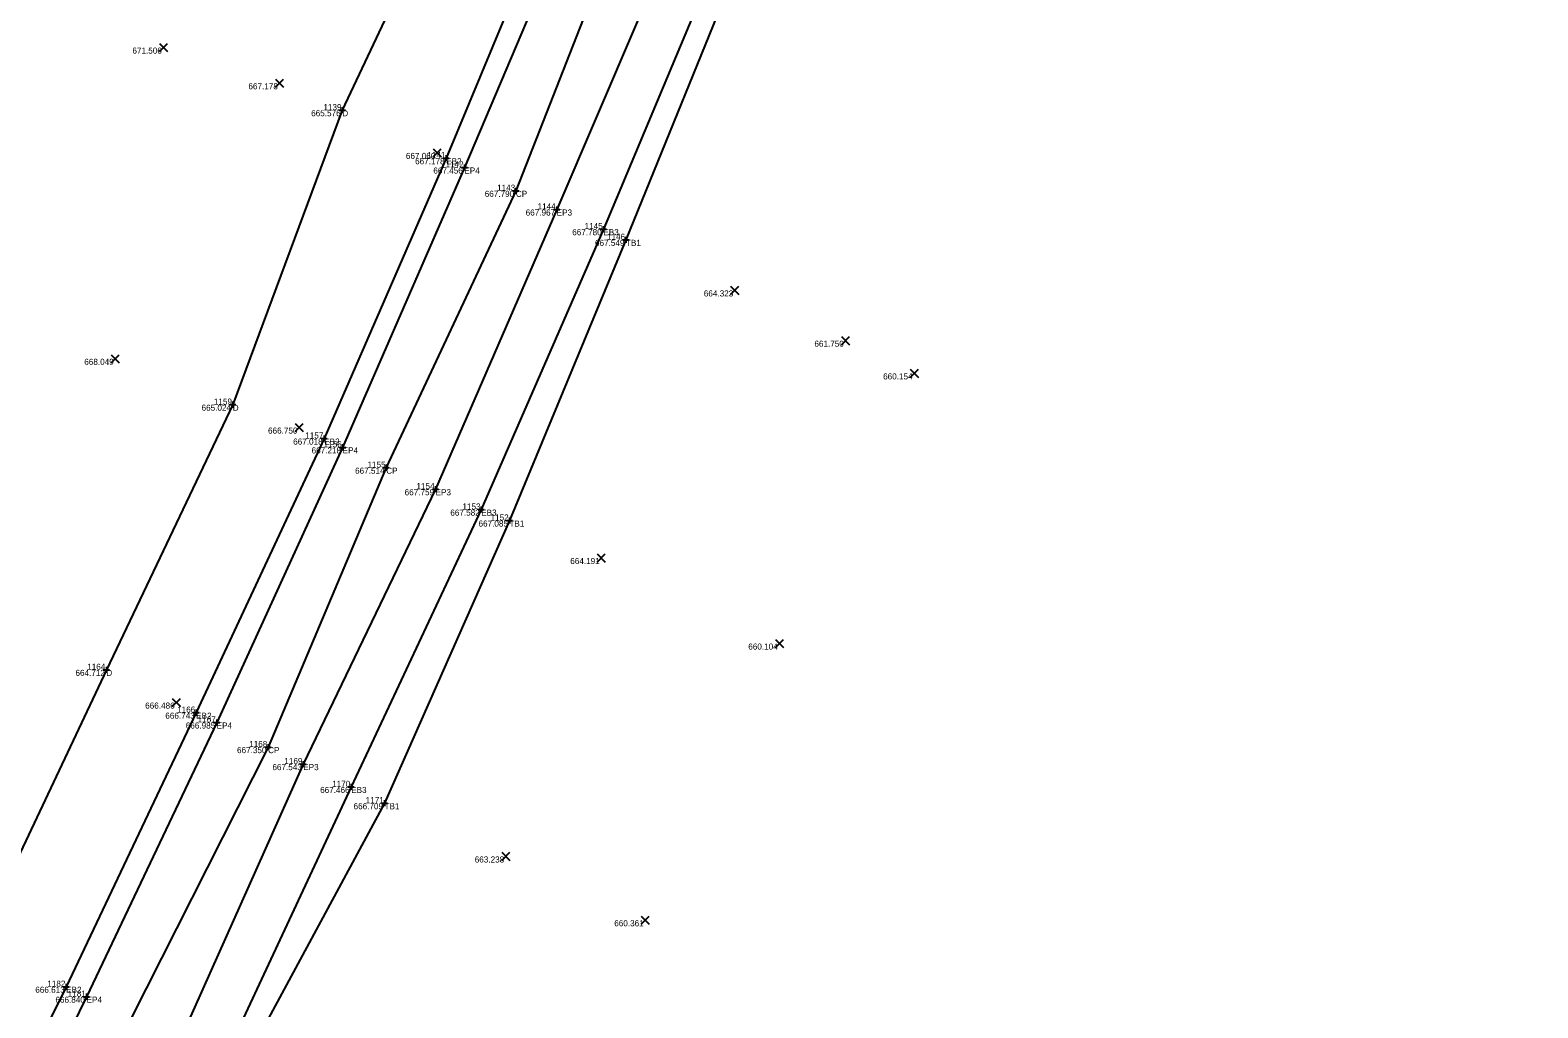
# Model space of a CAD drawing. Extents: x 2197382 to 2204062, y 634117 to 636522.
# Drawn here: x 2203093 to 2203340.5, y 635874.6 to 636035.1 of the extents above; entities that cross this region are included whole.
import ezdxf

# ---------------------------------------------------------------- set-up
doc = ezdxf.new("R2010")
doc.units = 0
for name, color, linetype in [('_CIVIL_CONSTRUCTION', 7, 'Continuous'), ('DR_X_Ditch', 7, 'Continuous'), ('GE_P_Alignment_100_Distances', 7, 'Continuous'), ('GE_X_Alignment', 7, 'Continuous'), ('PF_P_Grade_Line', 7, 'Continuous'), ('PV_X_COP', 7, 'Continuous'), ('RW_X_CL_100_Curve_Data', 7, 'Continuous'), ('SH_Border', 7, 'Continuous'), ('SH_Cut_Line', 7, 'Continuous'), ('SH_Data', 7, 'Continuous')]:
    doc.layers.add(name, color=color, linetype=linetype)

msp = doc.modelspace()

# ---------------------------------------------------------------- linework, layer by layer
at = {"layer": '_CIVIL_CONSTRUCTION'}
for p, q in [((2203143.75, 636021.99), (2203144.75, 636021.99)), ((2203144.25, 636022.49), (2203144.25, 636021.49)), ((2203144.25, 636021.99), (2203144.25, 636021.99)), ((2203160.8, 636014.11), (2203161.8, 636014.11)), ((2203161.3, 636014.61), (2203161.3, 636013.61)), ((2203161.3, 636014.11), (2203161.3, 636014.11)), ((2203163.79, 636012.58), (2203164.79, 636012.58)), ((2203164.29, 636013.08), (2203164.29, 636012.08)), ((2203164.29, 636012.58), (2203164.29, 636012.58)), ((2203172.24, 636008.76), (2203173.24, 636008.76)), ((2203172.74, 636009.26), (2203172.74, 636008.26)), ((2203172.74, 636008.76), (2203172.74, 636008.76)), ((2203178.94, 636005.69), (2203179.94, 636005.69)), ((2203179.44, 636006.19), (2203179.44, 636005.19)), ((2203179.44, 636005.69), (2203179.44, 636005.69)), ((2203186.6, 636002.46), (2203187.6, 636002.46)), ((2203187.1, 636002.96), (2203187.1, 636001.96)), ((2203187.1, 636002.46), (2203187.1, 636002.46)), ((2203190.81, 636001.21), (2203190.81, 636000.21)), ((2203190.31, 636000.71), (2203191.31, 636000.71)), ((2203190.81, 636000.71), (2203190.81, 636000.71)), ((2203125.77, 635973.65), (2203126.77, 635973.65)), ((2203126.27, 635974.15), (2203126.27, 635973.15)), ((2203126.27, 635973.65), (2203126.27, 635973.65)), ((2203141.29, 635968.59), (2203141.29, 635967.59)), ((2203140.79, 635968.09), (2203141.79, 635968.09)), ((2203141.29, 635968.09), (2203141.29, 635968.09)), ((2203143.81, 635966.64), (2203144.81, 635966.64)), ((2203144.31, 635967.14), (2203144.31, 635966.14)), ((2203144.31, 635966.64), (2203144.31, 635966.64)), ((2203151.47, 635963.81), (2203151.47, 635962.81)), ((2203150.97, 635963.31), (2203151.97, 635963.31)), ((2203151.47, 635963.31), (2203151.47, 635963.31)), ((2203159.06, 635959.77), (2203160.06, 635959.77)), ((2203159.56, 635960.27), (2203159.56, 635959.27)), ((2203159.56, 635959.77), (2203159.56, 635959.77)), ((2203166.55, 635956.43), (2203167.55, 635956.43)), ((2203167.05, 635956.93), (2203167.05, 635955.93)), ((2203167.05, 635956.43), (2203167.05, 635956.43)), ((2203171.18, 635954.63), (2203172.18, 635954.63)), ((2203171.68, 635955.13), (2203171.68, 635954.13)), ((2203171.68, 635954.63), (2203171.68, 635954.63)), ((2203105.02, 635930.12), (2203106.02, 635930.12)), ((2203105.52, 635930.62), (2203105.52, 635929.62)), ((2203105.52, 635930.12), (2203105.52, 635930.12)), ((2203119.76, 635923.09), (2203120.76, 635923.09)), ((2203120.26, 635923.59), (2203120.26, 635922.59)), ((2203120.26, 635923.09), (2203120.26, 635923.09)), ((2203123.63, 635921.98), (2203123.63, 635920.98)), ((2203123.13, 635921.48), (2203124.13, 635921.48)), ((2203123.63, 635921.48), (2203123.63, 635921.48)), ((2203131.58, 635917.44), (2203132.58, 635917.44)), ((2203132.08, 635917.94), (2203132.08, 635916.94)), ((2203132.08, 635917.44), (2203132.08, 635917.44)), ((2203137.34, 635914.65), (2203138.34, 635914.65)), ((2203137.84, 635915.15), (2203137.84, 635914.15)), ((2203137.84, 635914.65), (2203137.84, 635914.65)), ((2203145.21, 635910.9), (2203146.21, 635910.9)), ((2203145.71, 635911.4), (2203145.71, 635910.4)), ((2203145.71, 635910.9), (2203145.71, 635910.9)), ((2203150.69, 635908.23), (2203151.69, 635908.23)), ((2203151.19, 635908.73), (2203151.19, 635907.73)), ((2203151.19, 635908.23), (2203151.19, 635908.23)), ((2203098.42, 635878.1), (2203099.42, 635878.1)), ((2203098.92, 635878.6), (2203098.92, 635877.6)), ((2203098.92, 635878.1), (2203098.92, 635878.1)), ((2203101.78, 635876.46), (2203102.78, 635876.46)), ((2203102.28, 635876.96), (2203102.28, 635875.96)), ((2203102.28, 635876.46), (2203102.28, 635876.46))]:
    msp.add_line(p, q, dxfattribs=at)
at = {"layer": 'DR_X_Ditch'}
msp.add_lwpolyline([(2203184.1, 636112.24), (2203164.63, 636065.3), (2203144.25, 636021.99), (2203126.27, 635973.65), (2203105.52, 635930.12), (2203083.98, 635884.54), (2203067.89, 635850.01), (2203034.81, 635789.04), (2203015.61, 635755.76), (2202991.81, 635713.71), (2202963.02, 635673.98)], dxfattribs=at)
at = {"layer": 'GE_P_Alignment_100_Distances'}
for points in [[(2203324.48, 636507.85), (2203318.62, 636484.14), (2203306.91, 636435.63), (2203294.22, 636387.53), (2203281.02, 636340.01), (2203266.86, 636291.74), (2203251.88, 636244.73), (2203235.99, 636197.91), (2203219.31, 636150.6), (2203201.96, 636104.73), (2203183.73, 636058.36), (2203164.29, 636012.58), (2203144.31, 635966.64), (2203123.63, 635921.48), (2203102.28, 635876.46), (2203085.37, 635841.98), (2203051.94, 635779.64), (2203032.08, 635745.73), (2203005.62, 635703.58), (2202977.57, 635663.01), (2202948.44, 635623.54), (2202917.31, 635585.47), (2202885.13, 635547.53), (2202851.31, 635511.58)], [(2203340.49, 636502.89), (2203334.83, 636480.1), (2203323.13, 636431.59), (2203310.29, 636383.13), (2203297.23, 636335.04), (2203282.66, 636287.13), (2203267.38, 636239.56), (2203251.38, 636192.17), (2203234.81, 636145.08), (2203217.29, 636098.29), (2203199.14, 636051.74), (2203179.44, 636005.69), (2203159.56, 635959.77), (2203137.84, 635914.65), (2203117.45, 635869.06), (2203100.66, 635835.13), (2203066.13, 635771.41), (2203046.09, 635737.06), (2203019.37, 635694.82), (2202991.01, 635653.88), (2202961.19, 635613.48), (2202929.73, 635574.61), (2202897.41, 635536.46), (2202863.17, 635499.96)]]:
    msp.add_lwpolyline(points, dxfattribs=at)
at = {"layer": 'GE_X_Alignment'}
for points in [[(2203321.2, 636508.87), (2203315.42, 636484.99), (2203303.56, 636436.4), (2203290.91, 636388.48), (2203277.67, 636341.19), (2203263.29, 636292.83), (2203248.5, 636245.95), (2203232.65, 636199.01), (2203215.82, 636151.66), (2203198.58, 636105.93), (2203180.2, 636059.59), (2203161.3, 636014.11), (2203141.29, 635968.09), (2203120.26, 635923.09), (2203098.92, 635878.1), (2203081.73, 635843.65), (2203048.56, 635781.48), (2203029.15, 635747.49), (2203002.61, 635705.63), (2202974.64, 635665.31), (2202945.56, 635625.56), (2202914.38, 635588.2), (2202882.41, 635550.01), (2202847.99, 635514.11)], [(2203331.27, 636429.38), (2203318.29, 636380.99), (2203304.79, 636332.88), (2203290.18, 636284.77), (2203275.23, 636236.57), (2203259.29, 636189.41), (2203242.5, 636142.16), (2203224.73, 636095.35), (2203206.44, 636048.57), (2203187.1, 636002.46), (2203167.05, 635956.43), (2203145.71, 635910.9), (2203124.58, 635865.62), (2203107.54, 635831.47), (2203073.07, 635766.88), (2203053.33, 635732.69), (2203026.37, 635690.11), (2202997.51, 635648.24), (2202967.93, 635608.32), (2202935.99, 635569.18), (2202902.86, 635531.15), (2202868.61, 635494.33)]]:
    msp.add_lwpolyline(points, dxfattribs=at)
at = {"layer": 'PF_P_Grade_Line'}
msp.add_lwpolyline([(2203263.6, 636187.64), (2203248.97, 636139.91), (2203228.73, 636093.53), (2203209.69, 636047.17), (2203190.81, 636000.71), (2203171.68, 635954.63), (2203151.19, 635908.23), (2203127.58, 635864.5), (2203111.43, 635829.11), (2203075.98, 635764.92), (2203057.74, 635729.87), (2203030.91, 635688.09), (2203003.19, 635643.55), (2202971.04, 635606.63), (2202940.16, 635565.41)], dxfattribs=at)
at = {"layer": 'PV_X_COP'}
msp.add_lwpolyline([(2203333.12, 636504.55), (2203327.23, 636481.85), (2203314.64, 636433.62), (2203302.94, 636385.15), (2203289.25, 636336.51), (2203274.73, 636289.23), (2203259.31, 636242.63), (2203243.41, 636195.32), (2203226.43, 636148.15), (2203210.06, 636101.18), (2203190.93, 636055.28), (2203172.74, 636008.76), (2203151.47, 635963.31), (2203132.08, 635917.44), (2203109.53, 635872.8), (2203093.5, 635838.3), (2203058.15, 635776.21), (2203038.88, 635741.65), (2203011.92, 635699.74), (2202984.39, 635657.94), (2202954.68, 635618.56), (2202923.73, 635579.74), (2202891.73, 635541.49), (2202857.33, 635505.37)], dxfattribs=at)
at = {"layer": 'RW_X_CL_100_Curve_Data'}
for p, q in [((2203114.24, 636031.6), (2203115.57, 636032.93)), ((2203114.24, 636032.93), (2203115.57, 636031.6)), ((2203133.28, 636025.75), (2203134.61, 636027.08)), ((2203133.28, 636027.08), (2203134.61, 636025.75)), ((2203159.14, 636014.31), (2203160.47, 636015.65)), ((2203159.14, 636015.65), (2203160.47, 636014.31)), ((2203207.98, 635991.74), (2203209.32, 635993.08)), ((2203207.98, 635993.08), (2203209.32, 635991.74)), ((2203226.19, 635983.48), (2203227.52, 635984.82)), ((2203226.19, 635984.82), (2203227.52, 635983.48)), ((2203106.31, 635980.51), (2203107.65, 635981.85)), ((2203106.31, 635981.85), (2203107.65, 635980.51)), ((2203237.47, 635978.12), (2203238.81, 635979.45)), ((2203237.47, 635979.45), (2203238.81, 635978.12)), ((2203136.51, 635969.22), (2203137.84, 635970.55)), ((2203136.51, 635970.55), (2203137.84, 635969.22)), ((2203186.09, 635947.81), (2203187.42, 635949.15)), ((2203186.09, 635949.15), (2203187.42, 635947.81)), ((2203215.35, 635933.78), (2203216.68, 635935.11)), ((2203215.35, 635935.11), (2203216.68, 635933.78)), ((2203116.34, 635924.08), (2203117.67, 635925.42)), ((2203116.34, 635925.42), (2203117.67, 635924.08)), ((2203170.42, 635898.82), (2203171.76, 635900.16)), ((2203170.42, 635900.16), (2203171.76, 635898.82)), ((2203193.3, 635888.35), (2203194.64, 635889.69)), ((2203193.3, 635889.69), (2203194.64, 635888.35))]:
    msp.add_line(p, q, dxfattribs=at)

# ---------------------------------------------------------------- texts
at = {"layer": 'SH_Border'}
for s, p in [('D', (2203144.25, 636020.99)), ('EB2', (2203161.3, 636013.11)), ('EP4', (2203164.29, 636011.58)), ('CP', (2203172.74, 636007.76)), ('EP3', (2203179.44, 636004.69)), ('EB3', (2203187.1, 636001.46)), ('TB1', (2203190.81, 635999.71)), ('D', (2203126.27, 635972.65)), ('EB2', (2203141.29, 635967.09)), ('EP4', (2203144.31, 635965.64)), ('CP', (2203151.47, 635962.31)), ('EP3', (2203159.56, 635958.77)), ('EB3', (2203167.05, 635955.43)), ('TB1', (2203171.68, 635953.63)), ('D', (2203105.52, 635929.12)), ('EB2', (2203120.26, 635922.09)), ('EP4', (2203123.63, 635920.48)), ('CP', (2203132.08, 635916.44)), ('EP3', (2203137.84, 635913.65)), ('EB3', (2203145.71, 635909.9)), ('TB1', (2203151.19, 635907.23)), ('EB2', (2203098.92, 635877.1)), ('EP4', (2203102.28, 635875.46))]:
    msp.add_text(s, height=1, dxfattribs=at).set_placement(p)
at = {"layer": 'SH_Cut_Line'}
for s, p in [('1139', (2203141.15, 636021.99)), ('1141', (2203158.2, 636014.11)), ('1142', (2203161.2, 636012.58)), ('1143', (2203169.66, 636008.76)), ('1144', (2203176.3, 636005.69)), ('1145', (2203184.02, 636002.46)), ('1146', (2203187.69, 636000.71)), ('1159', (2203123.17, 635973.65)), ('1157', (2203138.17, 635968.09)), ('1156', (2203141.19, 635966.64)), ('1155', (2203148.38, 635963.31)), ('1154', (2203156.42, 635959.77)), ('1153', (2203163.97, 635956.43)), ('1152', (2203168.59, 635954.63)), ('1164', (2203102.38, 635930.12)), ('1166', (2203117.14, 635923.09)), ('1167', (2203120.51, 635921.48)), ('1168', (2203128.97, 635917.44)), ('1169', (2203134.74, 635914.65)), ('1170', (2203142.58, 635910.9)), ('1171', (2203148.09, 635908.23)), ('1182', (2203095.83, 635878.1)), ('1181', (2203099.18, 635876.46))]:
    msp.add_text(s, height=1, dxfattribs=at).set_placement(p)
at = {"layer": 'SH_Data'}
for s, p in [('671.506', (2203109.8, 636031.27)), ('667.178', (2203128.84, 636025.42)), ('665.576', (2203139.14, 636020.99)), ('667.060', (2203154.69, 636013.98)), ('667.178', (2203156.2, 636013.11)), ('667.456', (2203159.19, 636011.58)), ('667.790', (2203167.63, 636007.76)), ('667.967', (2203174.35, 636004.69)), ('667.780', (2203181.99, 636001.46)), ('667.549', (2203185.73, 635999.71)), ('664.323', (2203203.59, 635991.41)), ('661.750', (2203221.74, 635983.15)), ('668.049', (2203101.9, 635980.18)), ('660.154', (2203233.02, 635977.79)), ('665.024', (2203121.15, 635972.65)), ('666.750', (2203132.06, 635968.89)), ('667.018', (2203136.19, 635967.09)), ('667.218', (2203139.21, 635965.64)), ('667.514', (2203146.35, 635962.31)), ('667.759', (2203154.48, 635958.77)), ('667.582', (2203161.98, 635955.43)), ('667.085', (2203166.61, 635953.63)), ('664.191', (2203181.67, 635947.48)), ('660.104', (2203210.89, 635933.44)), ('664.712', (2203100.45, 635929.12)), ('666.486', (2203111.9, 635923.75)), ('666.743', (2203115.2, 635922.09)), ('666.985', (2203118.56, 635920.48)), ('667.350', (2203126.97, 635916.44)), ('667.543', (2203132.78, 635913.65)), ('667.466', (2203140.61, 635909.9)), ('666.709', (2203146.1, 635907.23)), ('663.238', (2203165.99, 635898.49)), ('660.361', (2203188.89, 635888.02)), ('666.613', (2203093.86, 635877.1)), ('666.840', (2203097.16, 635875.46))]:
    msp.add_text(s, height=1, dxfattribs=at).set_placement(p)

doc.saveas('drawing.dxf')
